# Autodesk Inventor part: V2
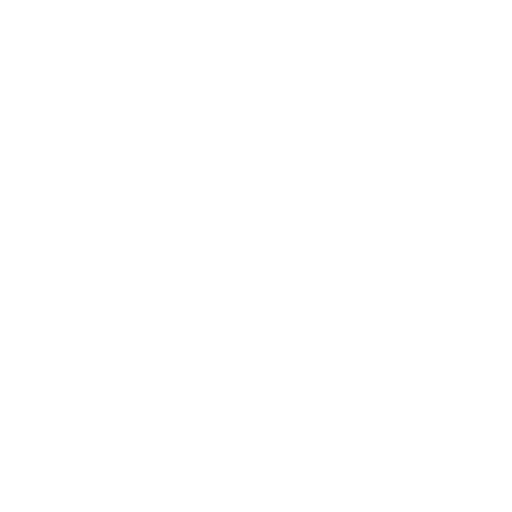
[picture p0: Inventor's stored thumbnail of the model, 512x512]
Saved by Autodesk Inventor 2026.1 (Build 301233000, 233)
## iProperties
Created: 2026-03
Part Number: V2
Material: Steel
Document SubType Name: Modeling
Designer: Yury Melnikov
Density: 7.85 g/cm^3
Appearance: По умолчанию
Title: V2.stp
Author: user
Sending System: Autodesk Inventor 2026
Preprocessor: ST-DEVELOPER v20.1
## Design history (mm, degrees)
node "Исправленная геометрия1"
  node "Эскиз311"
  node "Эскиз259"
  node "Эскиз292"
  node "Эскиз268"
  node "Эскиз265"
  node "Эскиз236"
  node "Эскиз223"
  node "Эскиз16"
feature "Шкивы"
feature "Шкивы:1"
feature "Шкивы:2"
feature "Шкивы:3"
feature "Лапки"
feature "Лапки:1"
feature "Лапки:2"
feature "Лапки:3"
feature "Дека"
feature "Шкив ведущий"
feature "Шкив ведомый"
feature "Крепление мотора"
feature "Крепление ведомого"
feature "Фанерка верх"
feature "Каретка"
feature "Рельса"
feature "Ремень"
feature "Рельса 2"
feature "Крепление ремня"
feature "Крепление ремня:1"
feature "Профиль"
feature "Профиль2"
feature "Крепление ниж мотора"
feature "Крепление ниж мотора:1"
feature "Заглушки"
feature "Заглушки:1"
feature "Стойки"
feature "Стойки:1"
feature "Стойки:2"
feature "Стойки:3"
feature "Плита"
feature "Плата"
feature "Лицевая панель"
feature "Направляющая"
feature "Подставка макетки"
feature "КонцевикУ"
feature "Корпус АКБ"
feature "Крышка"
feature "Подшипники"
feature "Подшипники:1"
feature "Подшипники:2"
feature "Подшипники:3"
feature "Каретка3"
feature "Проставки"
feature "Проставки:1"
feature "Проставки:2"
feature "Проставки:3"
feature "Пружина креп"
feature "Маркер креп"
feature "Цепь рама"
feature "Крепление датчика"
node "Твердое тело1"
node "Твердое тело2"
node "Твердое тело3"
node "Твердое тело4"
node "Твердое тело5"
node "Твердое тело6"
node "Твердое тело7"
node "Твердое тело8"
node "Твердое тело9"
node "Твердое тело10"
node "Твердое тело11"
node "Твердое тело12"
node "Твердое тело13"
node "Твердое тело14"
node "Твердое тело15"
node "Твердое тело16"
node "Твердое тело17"
node "Твердое тело18"
node "Твердое тело19"
node "Твердое тело20"
node "Твердое тело21"
node "Твердое тело22"
node "Твердое тело23"
node "Твердое тело24"
node "Твердое тело25"
node "Твердое тело26"
node "Твердое тело27"
node "Твердое тело28"
node "Твердое тело29"
node "Твердое тело30"
node "Твердое тело31"
node "Твердое тело32"
node "Твердое тело33"
node "Твердое тело34"
node "Твердое тело35"
node "Твердое тело36"
node "Твердое тело37"
node "Твердое тело38"
node "Твердое тело39"
node "Твердое тело40"
node "Твердое тело41"
node "Твердое тело42"
node "Твердое тело43"
node "Твердое тело44"
node "Твердое тело45"
node "Твердое тело46"
node "Твердое тело47"
node "Твердое тело48"
node "Твердое тело49"
node "Твердое тело50"
node "Твердое тело51"
